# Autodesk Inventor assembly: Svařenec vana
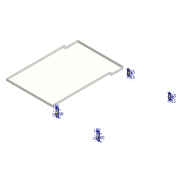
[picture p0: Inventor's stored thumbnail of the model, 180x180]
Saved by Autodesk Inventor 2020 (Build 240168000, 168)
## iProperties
Created: 2025-03
Part Number: Svařenec vana
Document SubType Name: Assembly
Designer: doma
Author: doma
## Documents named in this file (6)
- C:\Users\doma\Desktop\škola\DP\Inventor\Svařenec vana.iam
- C:\Users\doma\Desktop\škola\DP\Inventor\Klínek vany.ipt
- C:\Users\doma\Desktop\škola\DP\Inventor\Ústí vany.ipt
- C:\Users\doma\Desktop\škola\DP\Inventor\Vana.ipt
- C:\Users\doma\Desktop\škola\DP\Inventor\Zajištění vany 2.ipt
- C:\Users\doma\Desktop\škola\DP\Inventor\Zajištění vany 1.ipt
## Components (8 placed, 5 different names)
1. Klínek vany:1 — Stejný směr:2, Proti sobě:3, Proti sobě:4
2. Ústí vany:1 — Proti sobě:11, Proti sobě:12
3. Vana:1 — Stejný směr:1, Proti sobě:1, Proti sobě:2, Stejný směr:2, Proti sobě:3, Proti sobě:4, Proti sobě:9, Stejný směr:4, Stejný směr:5, Stejný směr:7, Stejný směr:8, Proti sobě:10, Stejný směr:9, Stejný směr:10, Stejný směr:11, Stejný směr:12, Proti sobě:11, Proti sobě:12
4. Klínek vany:2 — Stejný směr:1, Proti sobě:1, Proti sobě:2
5. Zajištění vany 2:1 — Stejný směr:6, Stejný směr:8, Stejný směr:10
6. Zajištění vany 2:2 — Stejný směr:6, Stejný směr:7, Proti sobě:10, Stejný směr:9
7. Zajištění vany 1:1 — Stejný směr:3, Stejný směr:5, Stejný směr:11
8. Zajištění vany 1:2 — Stejný směr:3, Proti sobě:9, Stejný směr:4, Stejný směr:12
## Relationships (20: Flush 12, Mate 8)
- Stejný směr:1 [Flush]: Vana:1 ↔ Klínek vany:2
- Proti sobě:1 [Mate]: Vana:1 ↔ Klínek vany:2
- Proti sobě:2 [Mate]: Vana:1 ↔ Klínek vany:2
- Stejný směr:2 [Flush]: Klínek vany:1 ↔ Vana:1
- Proti sobě:3 [Mate]: Klínek vany:1 ↔ Vana:1
- Proti sobě:4 [Mate]: Klínek vany:1 ↔ Vana:1
- Stejný směr:3 [Flush]: Zajištění vany 1:1 ↔ Zajištění vany 1:2
- Proti sobě:9 [Mate]: Vana:1 ↔ Zajištění vany 1:2
- Stejný směr:4 [Flush]: Vana:1 ↔ Zajištění vany 1:2
- Stejný směr:5 [Flush]: Vana:1 ↔ Zajištění vany 1:1
- Stejný směr:6 [Flush]: Zajištění vany 2:1 ↔ Zajištění vany 2:2
- Stejný směr:7 [Flush]: Vana:1 ↔ Zajištění vany 2:2
- Stejný směr:8 [Flush]: Vana:1 ↔ Zajištění vany 2:1
- Proti sobě:10 [Mate]: Vana:1 ↔ Zajištění vany 2:2
- Stejný směr:9 [Flush]: Vana:1 ↔ Zajištění vany 2:2
- Stejný směr:10 [Flush]: Vana:1 ↔ Zajištění vany 2:1
- Stejný směr:11 [Flush]: Vana:1 ↔ Zajištění vany 1:1
- Stejný směr:12 [Flush]: Vana:1 ↔ Zajištění vany 1:2
- Proti sobě:11 [Mate]: Ústí vany:1 ↔ Vana:1
- Proti sobě:12 [Mate]: Ústí vany:1 ↔ Vana:1
